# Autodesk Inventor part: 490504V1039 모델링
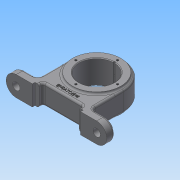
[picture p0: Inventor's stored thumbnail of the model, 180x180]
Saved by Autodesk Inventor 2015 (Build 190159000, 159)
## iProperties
Created: 2019-05
Part Number: 490504V1039 모델링
Material: 일반
Document SubType Name: Modeling
Designer: user
Density: 1 g/cm^3
Appearance: 기본값
Author: user
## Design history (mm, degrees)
sketch "스케치1"
  geometry: L1 (-75, -60)-(75, -60); L2 (-40, 0)-(-40, -48); L3 (40, 0)-(40, -48); L4 (-75, -48)-(-75, -60); L5 (75, -48)-(75, -60); L6 (75, -48)-(40, -48); L7 (-40, -48)-(-75, -48); A1 r 40 centre (0, 0) between (40, 0) and (-40, 0); 1 further point
  constraints: 14 end point, 2 point on circle, 1 centre point, 1 coincident, 1 parallel, 1 vertical
  dimensions: "d0" = 80 diameter of A1; "d3" = 150 distance between parallel lines of L5 L4
extrude "돌출1" new body sketch "스케치1" stored distance "d5" = 30; taper "d6" = 0 deg
fillet "모깎기1" dims "d7" = 15
node "작업 평면1"
sketch "스케치2"
  geometry: C1 r 36 at (0, 0); 1 further point
  constraints: 1 centre point, 1 coincident
  dimensions: "d9" = 72 diameter of C1
extrude "돌출2" join sketch "스케치2" stored distance "d10" = 36; taper "d11" = 0 deg
fillet "모깎기3" dims "d13" = 3
sketch "스케치3"
  geometry: C1 r 26 at (0, 0); A1 r 36 centre (0, 0) between (36, 0) and (36, 0) reference
  constraints: 1 centre point, 1 coincident
  dimensions: "d14" = 52 diameter of C1
extrude "돌출3" cut sketch "스케치3" stored distance "d15" = 36; taper "d16" = 0 deg
sketch "스케치4"
  geometry: L1 (-60, -60)-(60, -60) reference; L2 (-36, -60)-(36, -60); L3 (36, -60)-(36, -56); L4 (-36, -56)-(-36, -60); L5 (-30, -60)-(30, -60); L6 (30, -56)-(30, -50); L7 (30, -50)-(-30, -50); L8 (-30, -50)-(-30, -56); L9 (36, -56)-(30, -56); L10 (-30, -56)-(-36, -56); 6 further points
  constraints: 18 end point, 6 midpoint, 5 parallel, 4 coincident, 2 horizontal, 2 perpendicular
  dimensions: "d17" = 72 distance of L2.start L2.end; "d18" = 4 distance of L4.start L2.start; "d19" = 60 distance of L7.end L6.end; "d20" = 10 distance of L6.end L5.end
extrude "돌출4" cut sketch "스케치4" stored distance "d21" = 36; taper "d22" = 0 deg
fillet "모깎기4" dims "d23" = 3
fillet "모깎기5" dims "d24" = 6
fillet "모깎기6" dims "d25" = 3
sketch "스케치5"
  geometry: C1 r 9 at (0, -12); A1 r 12 centre (0, -12) between (0, 0) and (0, -24) reference; 1 further point
  constraints: 1 centre point, 1 coincident
  dimensions: "d26" = 18 diameter of C1
extrude "돌출5" join sketch "스케치5" distance "d27" = 3; taper "d28" = 0 deg
fillet "모깎기7" dims "d29" = 3
sketch "스케치6"
  geometry: C1 r 9 at (0, 0) reference; C2 r 5.5 at (0, 0); 1 further point
  constraints: 1 centre point, 1 coincident
  dimensions: "d30" = 11 diameter of C2
extrude "돌출6" cut sketch "스케치6" stored distance "d31" = 3; taper "d32" = 0 deg
node "작업 평면2"
fillet "모깎기8" dims "d34" = 3
fillet "모깎기9" dims "d35" = 3
sketch "스케치7"
  geometry: L1 (0, 0)-(0, 26); C1 r 36 at (0, 0) reference; C2 r 1.5 at (0, 26); 1 further point
  constraints: 2 end point, 1 centre point, 1 coincident, 1 vertical, 1 vertical alignment, 1 other
  dimensions: "d36" = 3 diameter of C2
extrude "돌출7" cut sketch "스케치7" stored distance "d37" = 3; taper "d38" = 0 deg
node "작업 평면3"
node "작업 평면4"
sketch "스케치9"
  geometry: L1 (0, -50)-(0, -43); L2 (-21.166, -39.71)-(21.166, -39.71); L3 (21.166, -39.71)-(21.166, -46.29); L4 (21.166, -46.29)-(-21.166, -46.29); L5 (-21.166, -46.29)-(-21.166, -39.71); 3 further points
  constraints: 2 end point, 2 horizontal alignment, 2 midpoint, 1 vertical, 1 vertical alignment, 2 other
  dimensions: "d52" = 7 distance of L1.start L1.end
extrude "돌출8" join sketch "스케치9" distance "d53" = 0.5; taper "d54" = 0 deg
chamfer "모따기1" distance "d55" = 1; stored, may be unused: second distance "d56" = 2, angle "d57" = 45 deg
sketch "스케치10"
  geometry: 1 further point
hole "구멍2" sketch "스케치10" at (0, 0) diameter "d58" = 4.917; stored, may be unused: countersink angle "d62" = 82 deg, drill point angle "d64" = 118 deg; dims "d59" = 8, "d60" = 7, "d61" = 1, "d63" = 10
sketch "스케치11"
  geometry: L1 (65.5, -60)-(65.5, -45) reference; L2 (65.5, -45)-(69, -45) reference; L3 (75, -51)-(75, -60) reference; L4 (75, -60)-(65.5, -60) reference; L5 (-69, -45)-(-65.5, -45) reference; L6 (-65.5, -45)-(-65.5, -60) reference; L7 (-65.5, -60)-(-75, -60) reference; L8 (-75, -60)-(-75, -51) reference; L9 (40, 0)-(40, -42) reference; L10 (46, -48)-(48, -48) reference; L11 (51, -45)-(54.5, -45) reference; L12 (54.5, -45)-(54.5, -60) reference; L13 (54.5, -60)-(36, -60) reference; L14 (36, -60)-(36, -56) reference; L15 (36, -56)-(30, -56) reference; L16 (30, -56)-(30, -53) reference; L17 (27, -50)-(-27, -50) reference; L18 (-30, -53)-(-30, -56) reference; L19 (-30, -56)-(-36, -56) reference; L20 (-36, -56)-(-36, -60) reference; L21 (-36, -60)-(-54.5, -60) reference; L22 (-54.5, -60)-(-54.5, -45) reference; L23 (-54.5, -45)-(-51, -45) reference; L24 (-48, -48)-(-46, -48) reference; L25 (-40, -42)-(-40, 0) reference; L26 (-3.5, 39.847)-(-3.5, 39) reference; L27 (-3.5, 39)-(-2.458, 39) reference; L28 (-2.458, 39)-(-2.458, 29) reference; L29 (-2.458, 29)-(0, 27.523) reference; L30 (0, 27.523)-(2.458, 29) reference; L31 (2.458, 29)-(2.458, 39) reference; L32 (2.458, 39)-(3.5, 39) reference; L33 (3.5, 39)-(3.5, 39.847) reference; L34 (-1, 28.144)-(0, 28.144); L35 (0, 24.508)-(-1, 24.508); L36 (-1, 24.508)-(-1, 28.144); L37 (0, 28.144)-(0, 24.508); A1 r 26 centre (0, 0) between (-1.499, 25.957) and (1.499, 25.957) reference; A2 r 1.5 centre (0, 26) between (1.499, 25.957) and (-1.499, 25.957) reference; A3 r 3 centre (72, -45) between (69, -45) and (72, -48) reference; A4 r 3 centre (72, -51) between (75, -51) and (72, -48) reference; A5 r 3 centre (-72, -45) between (-72, -48) and (-69, -45) reference; A6 r 3 centre (-72, -51) between (-72, -48) and (-75, -51) reference; A7 r 6 centre (46, -42) between (40, -42) and (46, -48) reference; A8 r 3 centre (48, -45) between (48, -48) and (51, -45) reference; A9 r 3 centre (27, -53) between (30, -53) and (27, -50) reference; A10 r 3 centre (-27, -53) between (-27, -50) and (-30, -53) reference; A11 r 3 centre (-48, -45) between (-51, -45) and (-48, -48) reference; A12 r 6 centre (-46, -42) between (-46, -48) and (-40, -42) reference; A13 r 40 centre (0, 0) between (-3.5, 39.847) and (-40, 0) reference; A14 r 40 centre (0, 0) between (40, 0) and (3.5, 39.847) reference; 1 further point
  constraints: 8 end point, 1 horizontal, 1 parallel, 1 vertical alignment
revolve "회전1" sketch "스케치11" stored, may be unused: angle "d67" = 90 deg
sketch "스케치12" dims "d68" = 62
  geometry: L1 (0, 0)-(-31, 0); C1 r 36 at (0, 0) reference
  constraints: 2 end point, 1 coincident, 1 horizontal, 1 horizontal alignment, 2 other
hole "구멍3" sketch "스케치12" at (-31, 0) diameter "d69" = 3.242; stored, may be unused: countersink angle "d73" = 90 deg, drill point angle "d75" = 118 deg; dims "d70" = 6, "d71" = 4, "d72" = 2, "d74" = 8
node "솔리드1"
mirror "대칭1"
pattern_circular "원형 패턴2" dims angle "d77" = 360 deg
mirror "대칭3"
node "절단 모서리 투영1"
other parameters: "d4" = 12, "d8" = 0, "d33" = 0, "d50" = 0
